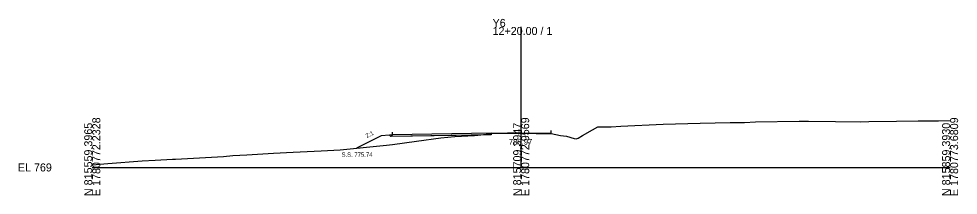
# Model space of a CAD drawing. Extents: x -26 to 1603, y -10 to 6024.
# Drawn here: x -25.7 to 302.8, y 2490.3 to 2551.9 of the extents above; entities that cross this region are included whole.
import ezdxf

# ---------------------------------------------------------------- set-up
doc = ezdxf.new("R2010")
doc.units = 0
for name, color, linetype in [('Exist Cross Section Cell', 7, 'Continuous'), ('Exist XS Center Line Elevation Label', 7, 'Continuous'), ('Exist XS Ground Line', 7, 'Continuous'), ('Prop XS Dump Level', 7, 'Continuous'), ('Prop XS Earthwork Shape', 7, 'Continuous'), ('Prop XS EOT Tick Mark', 7, 'Continuous'), ('Prop XS Finish Grade', 7, 'Continuous'), ('Prop XS Finish Grade Earthwork', 7, 'Continuous'), ('Prop XS Finish Grade Pavement', 7, 'Continuous'), ('Prop XS Pvmt Edge Slope', 7, 'Continuous'), ('Prop XS Side Slope Text', 7, 'Continuous'), ('Prop XS SS Elevation Text', 7, 'Continuous'), ('Prop XS Subgrade Earthwork', 7, 'Continuous')]:
    doc.layers.add(name, color=color, linetype=linetype)

msp = doc.modelspace()

# ---------------------------------------------------------------- linework, layer by layer
at = {"layer": 'Exist Cross Section Cell'}
for p, q in [((150, 2500), (150, 2549.07)), ((0, 2500), (150, 2500)), ((150, 2500), (300, 2500))]:
    msp.add_line(p, q, dxfattribs=at)
at = {"layer": 'Exist XS Ground Line'}
for p, q in [((174.94, 2513.17), (176.86, 2514.21)), ((176.86, 2514.21), (181.51, 2514.17)), ((181.51, 2514.17), (184.88, 2514.38)), ((184.88, 2514.38), (199.65, 2515.13)), ((199.65, 2515.13), (212.61, 2515.42)), ((212.61, 2515.42), (223.12, 2515.66)), ((223.12, 2515.66), (228.07, 2515.72)), ((228.07, 2515.72), (231.96, 2515.88)), ((231.96, 2515.88), (247.23, 2516.17)), ((247.23, 2516.17), (250.5, 2516.21)), ((250.5, 2516.21), (259.96, 2516.07)), ((259.96, 2516.07), (268.64, 2515.94)), ((268.64, 2515.94), (271.55, 2516.01)), ((271.55, 2516.01), (281.27, 2516.16)), ((281.27, 2516.16), (288.88, 2516.26)), ((288.88, 2516.26), (295.96, 2516.32)), ((295.96, 2516.32), (300, 2516.36)), ((113.35, 2509.15), (121.88, 2510.32)), ((121.88, 2510.32), (126.83, 2510.75)), ((126.83, 2510.75), (133.66, 2511.2)), ((133.66, 2511.2), (135.89, 2511.37)), ((135.89, 2511.37), (139.56, 2511.83)), ((139.56, 2511.83), (145.26, 2511.92)), ((145.26, 2511.92), (150.14, 2511.97)), ((150.14, 2511.97), (155.21, 2511.89)), ((155.21, 2511.89), (160.49, 2511.8)), ((160.49, 2511.8), (163.7, 2511.2)), ((163.7, 2511.2), (165.89, 2510.88)), ((165.89, 2510.88), (168.56, 2510.14)), ((168.56, 2510.14), (169.22, 2509.94)), ((169.22, 2509.94), (169.91, 2510.26)), ((169.91, 2510.26), (171.47, 2511.2)), ((171.47, 2511.2), (174.94, 2513.17)), ((86.73, 2506.18), (102.93, 2507.81)), ((102.93, 2507.81), (105.03, 2508.03)), ((105.03, 2508.03), (113.35, 2509.15)), ((29.17, 2502.89), (45.91, 2503.87)), ((45.91, 2503.87), (49.22, 2504.12)), ((49.22, 2504.12), (54.07, 2504.4)), ((54.07, 2504.4), (63.33, 2505.01)), ((63.33, 2505.01), (70.26, 2505.38)), ((70.26, 2505.38), (80.07, 2505.82)), ((80.07, 2505.82), (86.73, 2506.18)), ((0, 2500.96), (5.48, 2501.41)), ((5.48, 2501.41), (17.41, 2502.34)), ((17.41, 2502.34), (22.05, 2502.5)), ((22.05, 2502.5), (28.07, 2502.84)), ((28.07, 2502.84), (28.7, 2502.87)), ((28.7, 2502.87), (29.17, 2502.89))]:
    msp.add_line(p, q, dxfattribs=at)
at = {"layer": 'Prop XS Earthwork Shape'}
for points in [[(134.88, 2511.29), (104.41, 2510.77), (103.9, 2511.28), (101, 2511.06), (92.37, 2506.74), (102.93, 2507.81), (105.03, 2508.03), (113.35, 2509.15), (121.88, 2510.32), (126.83, 2510.75), (133.66, 2511.2)], [(134.88, 2511.29), (135.89, 2511.37), (139.56, 2511.83), (139.56, 2511.37)]]:
    msp.add_lwpolyline(points, close=True, dxfattribs=at)
at = {"layer": 'Prop XS EOT Tick Mark'}
for p, q in [((105, 2511.37), (105, 2512.37)), ((105, 2511.37), (105, 2512.37)), ((160.49, 2511.92), (160.49, 2512.92))]:
    msp.add_line(p, q, dxfattribs=at)
at = {"layer": 'Prop XS Finish Grade'}
msp.add_line((105, 2511.37), (103.9, 2511.28), dxfattribs=at)
at = {"layer": 'Prop XS Finish Grade Earthwork'}
for p, q in [((101, 2511.06), (92.37, 2506.74)), ((101, 2511.06), (92.37, 2506.74)), ((103.9, 2511.28), (101, 2511.06))]:
    msp.add_line(p, q, dxfattribs=at)
at = {"layer": 'Prop XS Finish Grade Pavement'}
for p, q in [((139.56, 2511.95), (105, 2511.37)), ((139.56, 2511.95), (105, 2511.37)), ((139.56, 2511.95), (145.26, 2512.05)), ((139.56, 2511.95), (139.57, 2511.83)), ((139.56, 2511.95), (139.57, 2511.83)), ((145.26, 2512.05), (150.14, 2512.1)), ((150.14, 2512.1), (155.21, 2512.01)), ((155.21, 2512.01), (160.49, 2511.92))]:
    msp.add_line(p, q, dxfattribs=at)
at = {"layer": 'Prop XS Pvmt Edge Slope'}
msp.add_line((105, 2511.37), (104.41, 2510.77), dxfattribs=at)
at = {"layer": 'Prop XS Subgrade Earthwork'}
for p, q in [((104.41, 2510.77), (103.9, 2511.28)), ((139.56, 2511.37), (104.41, 2510.77)), ((139.56, 2511.37), (139.56, 2511.83))]:
    msp.add_line(p, q, dxfattribs=at)

# ---------------------------------------------------------------- texts
at = {"layer": 'Exist Cross Section Cell'}
for s, p in [('Y6', (140, 2549.07)), ('12+20.00 / 1', (140, 2546.27)), ('EL 769', (-26, 2498.6))]:
    msp.add_text(s, height=2.8, dxfattribs=at).set_placement(p)
for s, p in [('E 1780772.2328', (2.8, 2490)), ('E 1780772.9569', (152.8, 2490)), ('E 1780773.6809', (302.8, 2490)), ('N 815559.3965', (0, 2490)), ('N 815709.3947', (150, 2490)), ('N 815859.3930', (300, 2490))]:
    msp.add_text(s, height=2.8, rotation=90, dxfattribs=at).set_placement(p)
at = {"layer": 'Exist XS Center Line Elevation Label'}
msp.add_text('780.97', height=2, dxfattribs=at).set_placement((145.7, 2507.97))
at = {"layer": 'Prop XS Dump Level'}
for s, height, p in [('Case1', 0.04, (101, 2511.02)), ('Case1', 0.04, (101, 2511.02)), ('Eop', 0.3, (139.56, 2511.53)), ('Eop', 0.3, (139.56, 2511.53))]:
    msp.add_text(s, height=height, dxfattribs=at).set_placement(p)
at = {"layer": 'Prop XS Side Slope Text'}
msp.add_text('2:1', height=1.5, rotation=26.5651, dxfattribs=at).set_placement((96.01, 2510.24))
msp.add_text('2:1', height=1.5, rotation=26.5651, dxfattribs=at).set_placement((96.01, 2510.24))
at = {"layer": 'Prop XS SS Elevation Text'}
msp.add_text('S.S. 775.74', height=1.5, dxfattribs=at).set_placement((87.18, 2503.74))
msp.add_text('S.S. 775.74', height=1.5, dxfattribs=at).set_placement((87.18, 2503.74))

doc.saveas('drawing.dxf')
